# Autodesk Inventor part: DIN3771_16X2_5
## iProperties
Created: 2007-03
Part Number: DIN3771_16X2_5
Document SubType Name: Modeling
Designer: Andy Moles
Material: Rubber
Mass: 0.265323 g
Surface Area: 4.56469 cm^2
Volume: 0.285293 cm^3
Density: 0.93 g/cm^3
Author: Andy Moles
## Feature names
1. Base1
